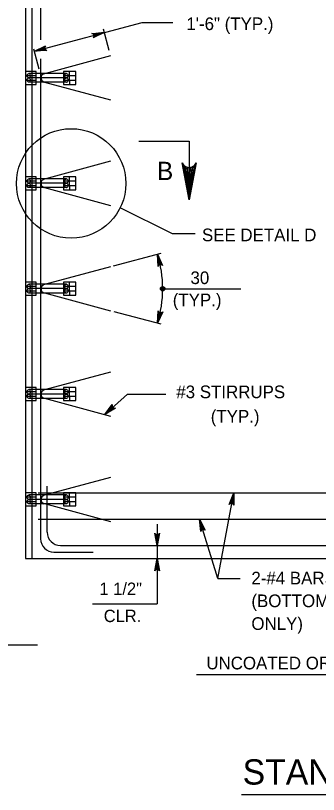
# Model space of a CAD drawing. Extents: x 3385 to 6532, y -616 to 1166.
# Drawn here: x 4745.6 to 4819.3, y 272.4 to 461.6 of the extents above; entities that cross this region are included whole.
import ezdxf

# ---------------------------------------------------------------- set-up
doc = ezdxf.new("R2010")
doc.units = 0
doc.layers.add('1', color=7, linetype='Continuous')

msp = doc.modelspace()

# ---------------------------------------------------------------- linework, layer by layer
at = {"layer": '1'}
for p, q in [((4748.02, 484.9), (4748.02, 329.7)), ((4749.58, 484.9), (4749.58, 329.7)), ((4751.71, 480.1), (4751.71, 455.77)), ((4750.18, 452.97), (4776.44, 460)), ((4776.44, 460), (4783.87, 460)), ((4768.36, 453.18), (4766.97, 458.35)), ((4751.34, 448.62), (4750.04, 453.49)), ((4751.71, 451.1), (4751.71, 334.5)), ((4768.72, 451.84), (4752.61, 447.52)), ((4757.99, 447.57), (4748.83, 447.57)), ((4758.75, 445.97), (4758.75, 448.1)), ((4757.99, 446.5), (4748.83, 446.5)), ((4757.99, 445.44), (4748.83, 445.44)), ((4752.61, 445.46), (4768.72, 441.14)), ((4758.75, 445.97), (4758.75, 444.9)), ((4775.6, 431.16), (4787.87, 431.16)), ((4787.87, 431.16), (4787.87, 416.9)), ((4768.72, 426.24), (4752.61, 421.92)), ((4758.75, 420.37), (4758.75, 422.5)), ((4757.99, 421.97), (4748.83, 421.97)), ((4757.99, 420.9), (4748.83, 420.9)), ((4758.75, 420.37), (4758.75, 419.3)), ((4757.99, 419.84), (4748.83, 419.84)), ((4752.61, 419.86), (4768.72, 415.54)), ((4783.76, 408.59), (4771.04, 414.93)), ((4789.35, 408.59), (4783.76, 408.59)), ((4769.42, 400.83), (4781.04, 403.94)), ((4768.72, 400.64), (4752.61, 396.32)), ((4757.99, 396.37), (4748.83, 396.37)), ((4758.75, 394.77), (4758.75, 396.9)), ((4757.99, 395.3), (4748.83, 395.3)), ((4757.99, 394.24), (4748.83, 394.24)), ((4752.61, 394.26), (4768.72, 389.94)), ((4758.75, 394.77), (4758.75, 393.7)), ((4781.41, 395.29), (4800.47, 395.29)), ((4781.04, 386.64), (4769.64, 389.7)), ((4768.72, 375.04), (4752.61, 370.72)), ((4758.75, 369.17), (4758.75, 371.3)), ((4757.99, 370.77), (4748.83, 370.77)), ((4757.99, 369.7), (4748.83, 369.7)), ((4758.75, 369.17), (4758.75, 368.1)), ((4772.84, 369.64), (4767.29, 364.73)), ((4772.84, 369.64), (4782.17, 369.64)), ((4757.99, 368.64), (4748.83, 368.64)), ((4752.61, 368.66), (4768.72, 364.34)), ((4768.72, 349.44), (4752.61, 345.12)), ((4753.31, 336.1), (4753.31, 347.3)), ((4757.99, 345.17), (4748.83, 345.17)), ((4751.08, 345.7), (4936.9, 345.7)), ((4758.75, 343.57), (4758.75, 345.7)), ((4794.84, 324.9), (4798.7, 345.7)), ((4757.99, 344.1), (4748.83, 344.1)), ((4757.99, 343.04), (4748.83, 343.04)), ((4752.61, 343.06), (4768.72, 338.75)), ((4758.75, 343.57), (4758.75, 342.5)), ((4751.08, 339.3), (4936.9, 339.3)), ((4794.84, 324.9), (4790.38, 339.3)), ((4780.05, 338.1), (4780.05, 318.71)), ((4754.91, 331.3), (4764.51, 331.3)), ((4756.51, 332.9), (4929.53, 332.9)), ((4748.02, 329.7), (4941.32, 329.7)), ((4794.84, 324.9), (4800.26, 324.9)), ((4764.35, 318.71), (4780.05, 318.71)), ((4699.21, 308.74), (4750.96, 308.74)), ((4789.62, 301.58), (4944.95, 301.58)), ((4800.63, 272.42), (4883.71, 272.42))]:
    msp.add_line(p, q, dxfattribs=at)
for points in [[(4767.2, 457.53), (4764.46, 456.22), (4764.64, 456.43), (4764.7, 456.65), (4764.68, 456.86), (4764.6, 457.04), (4764.43, 457.2), (4764.17, 457.3), (4767.2, 457.53), (4764.43, 457.2), (4764.6, 457.04), (4767.2, 457.53), (4764.68, 456.86), (4764.7, 456.65), (4767.2, 457.53), (4764.64, 456.43)], [(4750.18, 452.97), (4752.92, 454.28), (4752.74, 454.07), (4752.67, 453.84), (4752.69, 453.64), (4752.78, 453.46), (4752.94, 453.3), (4753.21, 453.2), (4750.18, 452.97), (4752.94, 453.3), (4752.78, 453.46), (4750.18, 452.97), (4752.69, 453.64), (4752.67, 453.84), (4750.18, 452.97), (4752.74, 454.07)], [(4787.87, 416.9), (4786.19, 425.84), (4786.43, 425.5), (4786.67, 425.16), (4786.97, 424.98), (4787.27, 424.8), (4787.57, 424.75), (4787.87, 424.7), (4788.17, 424.75), (4788.47, 424.8), (4788.77, 424.98), (4789.07, 425.16), (4789.3, 425.5), (4789.54, 425.84), (4787.87, 416.9), (4789.3, 425.5), (4789.07, 425.16), (4787.87, 416.9), (4788.77, 424.98), (4788.47, 424.8), (4787.87, 416.9), (4788.17, 424.75), (4787.87, 424.7), (4787.87, 416.9), (4787.57, 424.75), (4787.27, 424.8), (4787.87, 416.9), (4786.97, 424.98), (4786.67, 425.16), (4787.87, 416.9), (4786.43, 425.5)], [(4780.14, 403.7), (4781.39, 400.93), (4781.28, 401.03), (4781.18, 401.12), (4781.07, 401.15), (4780.96, 401.19), (4780.86, 401.18), (4780.75, 401.17), (4780.66, 401.13), (4780.57, 401.09), (4780.48, 401.01), (4780.4, 400.93), (4780.35, 400.8), (4780.3, 400.67), (4780.14, 403.7), (4780.35, 400.8), (4780.4, 400.93), (4780.14, 403.7), (4780.48, 401.01), (4780.57, 401.09), (4780.14, 403.7), (4780.66, 401.13), (4780.75, 401.17), (4780.14, 403.7), (4780.86, 401.18), (4780.96, 401.19), (4780.14, 403.7), (4781.07, 401.15), (4781.18, 401.12), (4780.14, 403.7), (4781.28, 401.03)], [(4780.14, 386.88), (4780.33, 389.91), (4780.38, 389.78), (4780.42, 389.65), (4780.51, 389.57), (4780.59, 389.49), (4780.68, 389.45), (4780.78, 389.41), (4780.88, 389.4), (4780.98, 389.39), (4781.09, 389.42), (4781.2, 389.46), (4781.31, 389.55), (4781.41, 389.64), (4780.14, 386.88), (4781.31, 389.55), (4781.2, 389.46), (4780.14, 386.88), (4781.09, 389.42), (4780.98, 389.39), (4780.14, 386.88), (4780.88, 389.4), (4780.78, 389.41), (4780.14, 386.88), (4780.68, 389.45), (4780.59, 389.49), (4780.14, 386.88), (4780.51, 389.57), (4780.42, 389.65), (4780.14, 386.88), (4780.38, 389.78)], [(4767.29, 364.73), (4769.15, 367.12), (4769.09, 366.85), (4769.13, 366.62), (4769.24, 366.45), (4769.4, 366.32), (4769.62, 366.25), (4769.9, 366.29), (4767.29, 364.73), (4769.62, 366.25), (4769.4, 366.32), (4767.29, 364.73), (4769.24, 366.45), (4769.13, 366.62), (4767.29, 364.73), (4769.09, 366.85)], [(4798.7, 345.7), (4798.71, 342.67), (4798.65, 342.8), (4798.59, 342.92), (4798.5, 343), (4798.42, 343.08), (4798.32, 343.11), (4798.23, 343.15), (4798.12, 343.15), (4798.02, 343.15), (4797.91, 343.11), (4797.81, 343.07), (4797.71, 342.97), (4797.61, 342.87), (4798.7, 345.7), (4797.71, 342.97), (4797.81, 343.07), (4798.7, 345.7), (4797.91, 343.11), (4798.02, 343.15), (4798.7, 345.7), (4798.12, 343.15), (4798.23, 343.15), (4798.7, 345.7), (4798.32, 343.11), (4798.42, 343.08), (4798.7, 345.7), (4798.5, 343), (4798.59, 342.92), (4798.7, 345.7), (4798.65, 342.8)], [(4790.38, 339.3), (4791.79, 336.62), (4791.68, 336.71), (4791.57, 336.79), (4791.46, 336.82), (4791.35, 336.85), (4791.25, 336.83), (4791.15, 336.82), (4791.06, 336.77), (4790.97, 336.73), (4790.89, 336.64), (4790.81, 336.56), (4790.77, 336.42), (4790.73, 336.29), (4790.38, 339.3), (4790.77, 336.42), (4790.81, 336.56), (4790.38, 339.3), (4790.89, 336.64), (4790.97, 336.73), (4790.38, 339.3), (4791.06, 336.77), (4791.15, 336.82), (4790.38, 339.3), (4791.25, 336.83), (4791.35, 336.85), (4790.38, 339.3), (4791.46, 336.82), (4791.57, 336.79), (4790.38, 339.3), (4791.68, 336.71)], [(4780.05, 332.9), (4779.49, 335.89), (4779.57, 335.77), (4779.65, 335.66), (4779.75, 335.6), (4779.85, 335.54), (4779.95, 335.52), (4780.05, 335.5), (4780.15, 335.52), (4780.25, 335.54), (4780.35, 335.6), (4780.45, 335.66), (4780.53, 335.77), (4780.61, 335.89), (4780.05, 332.9), (4780.53, 335.77), (4780.45, 335.66), (4780.05, 332.9), (4780.35, 335.6), (4780.25, 335.54), (4780.05, 332.9), (4780.15, 335.52), (4780.05, 335.5), (4780.05, 332.9), (4779.95, 335.52), (4779.85, 335.54), (4780.05, 332.9), (4779.75, 335.6), (4779.65, 335.66), (4780.05, 332.9), (4779.57, 335.77)], [(4780.05, 329.7), (4780.61, 326.72), (4780.53, 326.84), (4780.45, 326.95), (4780.35, 327.01), (4780.25, 327.07), (4780.15, 327.09), (4780.05, 327.1), (4779.95, 327.09), (4779.85, 327.07), (4779.75, 327.01), (4779.65, 326.95), (4779.57, 326.84), (4779.49, 326.72), (4780.05, 329.7), (4779.57, 326.84), (4779.65, 326.95), (4780.05, 329.7), (4779.75, 327.01), (4779.85, 327.07), (4780.05, 329.7), (4779.95, 327.09), (4780.05, 327.1), (4780.05, 329.7), (4780.15, 327.09), (4780.25, 327.07), (4780.05, 329.7), (4780.35, 327.01), (4780.45, 326.95), (4780.05, 329.7), (4780.53, 326.84)]]:
    msp.add_lwpolyline(points, dxfattribs=at)
for points in [[(4748.02, 445.97), (4750.64, 445.97), (4750.64, 448.1), (4748.02, 448.1)], [(4748.02, 444.9), (4750.64, 444.9), (4750.64, 447.03), (4748.02, 447.03)], [(4757.24, 445.97), (4760.25, 445.97), (4760.25, 448.1), (4757.24, 448.1)], [(4757.24, 444.9), (4760.25, 444.9), (4760.25, 447.03), (4757.24, 447.03)], [(4748.02, 420.37), (4750.64, 420.37), (4750.64, 422.5), (4748.02, 422.5)], [(4757.24, 420.37), (4760.25, 420.37), (4760.25, 422.5), (4757.24, 422.5)], [(4748.02, 419.3), (4750.64, 419.3), (4750.64, 421.43), (4748.02, 421.43)], [(4757.24, 419.3), (4760.25, 419.3), (4760.25, 421.43), (4757.24, 421.43)], [(4748.02, 394.77), (4750.64, 394.77), (4750.64, 396.9), (4748.02, 396.9)], [(4748.02, 393.7), (4750.64, 393.7), (4750.64, 395.83), (4748.02, 395.83)], [(4757.24, 394.77), (4760.25, 394.77), (4760.25, 396.9), (4757.24, 396.9)], [(4757.24, 393.7), (4760.25, 393.7), (4760.25, 395.83), (4757.24, 395.83)], [(4748.02, 369.17), (4750.64, 369.17), (4750.64, 371.3), (4748.02, 371.3)], [(4757.24, 369.17), (4760.25, 369.17), (4760.25, 371.3), (4757.24, 371.3)], [(4748.02, 368.1), (4750.64, 368.1), (4750.64, 370.24), (4748.02, 370.24)], [(4757.24, 368.1), (4760.25, 368.1), (4760.25, 370.23), (4757.24, 370.23)], [(4748.02, 343.57), (4750.64, 343.57), (4750.64, 345.7), (4748.02, 345.7)], [(4748.02, 342.5), (4750.64, 342.5), (4750.64, 344.64), (4748.02, 344.64)], [(4757.24, 343.57), (4760.25, 343.57), (4760.25, 345.7), (4757.24, 345.7)], [(4757.24, 342.5), (4760.25, 342.5), (4760.25, 344.63), (4757.24, 344.63)]]:
    msp.add_lwpolyline(points, close=True, dxfattribs=at)
for centre, radius in [((4759.13, 420.86), 13.31), ((4781.41, 395.29), 0.533), ((4781.41, 395.29), 0.267)]:
    msp.add_circle(centre, radius, dxfattribs=at)
for centre, radius, start, end in [((4752.88, 446.49), 1.07, 105, 255), ((4752.88, 420.89), 1.07, 105, 255), ((4752.88, 395.29), 28.53, 342.8582, 17.1418), ((4752.88, 395.29), 1.07, 105, 255), ((4752.88, 369.69), 1.07, 105, 255), ((4752.88, 344.09), 1.07, 105, 255), ((4756.51, 336.1), 3.2, 180, 270), ((4754.91, 334.5), 3.2, 180, 270)]:
    msp.add_arc(centre, radius, start, end, dxfattribs=at)
for centre, major_axis, ratio in [((4748.83, 447.03), (0, 0.534), 0.741868), ((4757.99, 447.04), (0, 0.534), 0.741868), ((4748.83, 445.97), (0, 0.531), 0.745444), ((4757.99, 445.96), (0, 0.534), 0.741868), ((4748.83, 421.43), (0, 0.534), 0.741868), ((4748.83, 420.37), (0, 0.531), 0.745444), ((4757.99, 421.44), (0, 0.534), 0.741868), ((4757.99, 420.36), (0, 0.534), 0.741868), ((4748.83, 395.83), (0, 0.534), 0.741868), ((4757.99, 395.84), (0, 0.534), 0.741868), ((4748.83, 394.77), (0, 0.531), 0.745444), ((4757.99, 394.76), (0, 0.534), 0.741868), ((4748.83, 370.23), (0, 0.534), 0.741868), ((4748.83, 369.17), (0, 0.531), 0.745444), ((4757.99, 370.24), (0, 0.534), 0.741868), ((4757.99, 369.16), (0, 0.534), 0.741868), ((4748.83, 344.63), (0, 0.534), 0.741868), ((4757.99, 344.64), (0, 0.534), 0.741868), ((4748.83, 343.57), (0, 0.531), 0.745444), ((4757.99, 343.57), (0, 0.534), 0.741868)]:
    msp.add_ellipse(centre, major_axis=major_axis, ratio=ratio, dxfattribs=at)

# ---------------------------------------------------------------- texts
for s, height, p in [('1\'-6" (TYP.)', 3.072, (4787.18, 458.12)), ('B', 4.45, (4780.01, 421.68)), ('SEE DETAIL D', 3.072, (4790.97, 406.82)), ('30', 3.072, (4788.18, 396.41)), ('(TYP.)', 3.072, (4783.86, 391.04)), ('#3 STIRRUPS', 3.072, (4784.73, 368.69)), ('(TYP.)', 3.072, (4793.11, 362.74)), ('2-#4 BARS ', 3.072, (4803, 323.45)), ('1 1/2"', 3, (4766.02, 320.89)), ('(BOTTOM PANEL ', 3.0721, (4803, 317.92)), ('CLR.', 3, (4767.06, 314.29)), ('ONLY)', 3.072, (4803, 312.39)), ('UNCOATED OR GALVANIZED - 1\'-7" MIN. (TYP.)', 3.072, (4792.04, 302.8)), ('STANDARD PANEL', 6.144, (4800.87, 274.81))]:
    msp.add_text(s, height=height, dxfattribs=at).set_placement(p)

doc.saveas('drawing.dxf')
